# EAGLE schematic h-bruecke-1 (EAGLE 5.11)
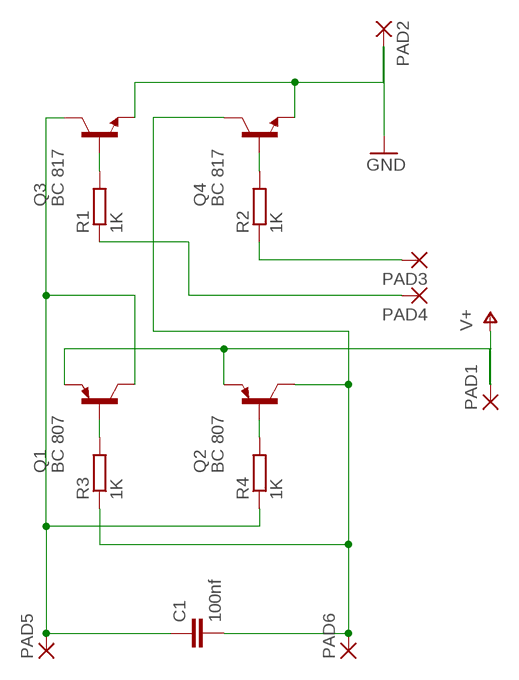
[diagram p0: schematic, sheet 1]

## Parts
C1  100nf  C-EUC0805K  [C0805K]
PAD1  2,15/1,0  [2,15/1,0]
PAD2  2,15/1,0  [2,15/1,0]
PAD3  2,15/1,0  [2,15/1,0]
PAD4  2,15/1,0  [2,15/1,0]
PAD5  2,15/1,0  [2,15/1,0]
PAD6  2,15/1,0  [2,15/1,0]
Q1  BC 807  BF821SMD  [SOT23-BEC]
Q2  BC 807  BF821SMD  [SOT23-BEC]
Q3  BC 817  BC850SMD  [SOT23-BEC]
Q4  BC 817  BC850SMD  [SOT23-BEC]
R1  1K  R-EU_R0805  [R0805]
R2  1K  R-EU_R0805  [R0805]
R3  1K  R-EU_R0805  [R0805]
R4  1K  R-EU_R0805  [R0805]

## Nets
GND: PAD2.1(P) Q3.E Q4.E
N$1: Q3.B R1.2
N$2: Q4.B R2.2
N$3: C1.1 PAD5.1(P) Q1.C Q3.C R4.1
N$4: C1.2 PAD6.1(P) Q2.C Q4.C R3.1
N$5: Q2.B R4.2
N$6: Q1.B R3.2
N$8: PAD4.1(P) R1.1
N$9: PAD3.1(P) R2.1
V+: PAD1.1(P) Q1.E Q2.E

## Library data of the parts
C1 = rcl:C-EU: CAPACITOR, European symbol
PAD1-PAD6 = wirepad:2,15/1,0: THROUGH-HOLE PAD
Q1 Q2 = transistor-pnp:BF821*: PNP Transistror
Q3 Q4 = transistor-npn:BC850*: NPN Transistor
R1-R4 = rcl:R-EU_: RESISTOR, European symbol

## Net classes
0 default: width 0.254 mm, clearance 0.254 mm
